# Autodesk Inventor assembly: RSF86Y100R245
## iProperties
Created: 2007-10
Part Number: RSF86Y100R245
Document SubType Name: Assembly
Designer: TMT
Description: Schwimmschalter
Author: TMT
Comments: CYNERGY3
